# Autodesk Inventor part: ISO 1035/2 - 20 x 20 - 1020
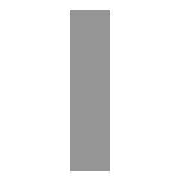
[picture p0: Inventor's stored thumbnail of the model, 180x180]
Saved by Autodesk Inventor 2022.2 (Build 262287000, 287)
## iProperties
_CCFamilyMember: 168
_CCFamilyDisplayName: ISO 1035/2 - 1980 - Barre in acciaio laminate a caldo - Parte 2: barre quadre
_FrameMemberDoc: Frame Member File
_Version: 25.0.0
_GetPNFromCC: 1
Created: 2025-02
Part Number: ISO 1035/2 - 20 x 20 - 1020
Material: Acciaio, Dolce
Description: Barre in acciaio laminate a caldo - Parte 2: barre quadre
Document SubType Name: Modeling
Standard: ISO 1035/2
Designer: 18907419
Standard Revision: First edition 1980-10-15
Standards Organization: ISO
Language: it-IT
Size Designation: 20x 20
Categories: <MemberInstance><Categories><Category DisplayName="Forme strutturali" InternalName="089c4875-fa83-4c05-b084-43b9cc11f5ed" Mnemonic="GRDR"><CategoryParameter Dis
Stock Number: 20x 20
Density: 7.85 g/cm^3
Appearance: Semilucidato
IsCustomPart: 1
G_L: 1020,000 mm
G_W: 20,000 mm
G_H: 20,000 mm
+374DB05E-BE82-4ECA-88F7-B26F20248773+CUTDETAIL1: Angolo retto 45,00 gr
+3A27C3CC-6522-4282-AD02-8628071835D6+CUTDETAIL2: Angolo retto 45,00 gr
+520B30BA-A766-466E-8C54-70492AFF0E80+CUTDETAIL3: Angolo retto 45,00 gr
+D24304F4-30FF-4AC0-819F-7BAAFB98F68D+CUTDETAIL4: Angolo retto 45,00 gr
Author: 18907419
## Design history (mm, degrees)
node "Piano iniziale"
node "Piano finale"
sketch "Schizzo"
  geometry: L1 (10, -10)-(-10, -10); L2 (-10, -10)-(-10, 10); L3 (-10, 10)-(10, 10); L4 (10, 10)-(10, -10); L5 (-6, 0)-(8, 0); L6 (0, -30)-(0, 40); L7 (0, 54)-(0, -44) reference; L8 (-14, 0)-(14, 0) reference
  constraints: 12 end point, 2 collinear, 2 parallel, 1 horizontal, 1 perpendicular
  dimensions: "d0" = 20 distance between parallel lines of L3 L1 (= G_W); "d1" = 20 distance between parallel lines of L4 L2 (= G_H); "d4" = 10 distance between parallel lines of L6 L4 (= 0.5 x d1); "d5" = 10 distance between parallel lines of L5 L3 (= 0.5 x d0)
extrude "Corpo" new body sketch "Schizzo" stored distance "d2" = 1020 (= G_L); taper "d3" = 0 deg
node "Driven Length"
  sketch "Sketch3"
    geometry: L1 (0, 0)-(10, 0) reference
    constraints: 2 end point, 1 horizontal
  workplane "Work Plane3"
  sketch "Sketch4"
    geometry: L1 (-2, -10)-(12, -10) reference; L2 (-2, 1010)-(12, 1010) reference
    dimensions: "d9" = 1020 dimension on L1 L2 (derived)
node "Piano di lavoro4"
feature "Divisione1"
node "Piano di lavoro5"
feature "Divisione2"
node "Piano di lavoro6"
feature "Divisione3"
node "Piano di lavoro7"
feature "Divisione4"
body "Solid1"
other parameters: "G_W" = 20 [user parameter; used in 1 equation term], "G_H" = 20 [user parameter; used in 1 equation term], "G_L" = 1020 (= d9) [user parameter; used in 1 equation term], "d8" = 90 deg
